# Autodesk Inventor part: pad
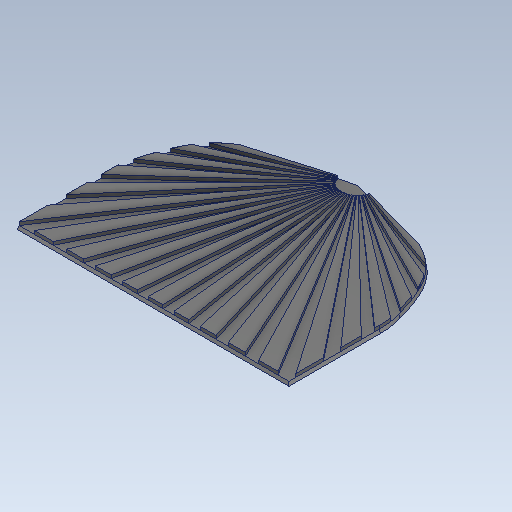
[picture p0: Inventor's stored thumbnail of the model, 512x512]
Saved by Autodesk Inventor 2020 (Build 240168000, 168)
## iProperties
Created: 2017-04
Part Number: pad
Material: Générique
Document SubType Name: Modeling
Designer: bruno
Density: 1 g/cm^3
Appearance: Par défaut
Author: bruno
Sending System: SolidWorks 2016
Last Author: Samartha
Last Saved: 2017-04-03
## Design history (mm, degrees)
feature "Boss-Extrude7"
node "Solide1"
